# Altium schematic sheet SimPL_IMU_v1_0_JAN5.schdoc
size 302 x 236 mm
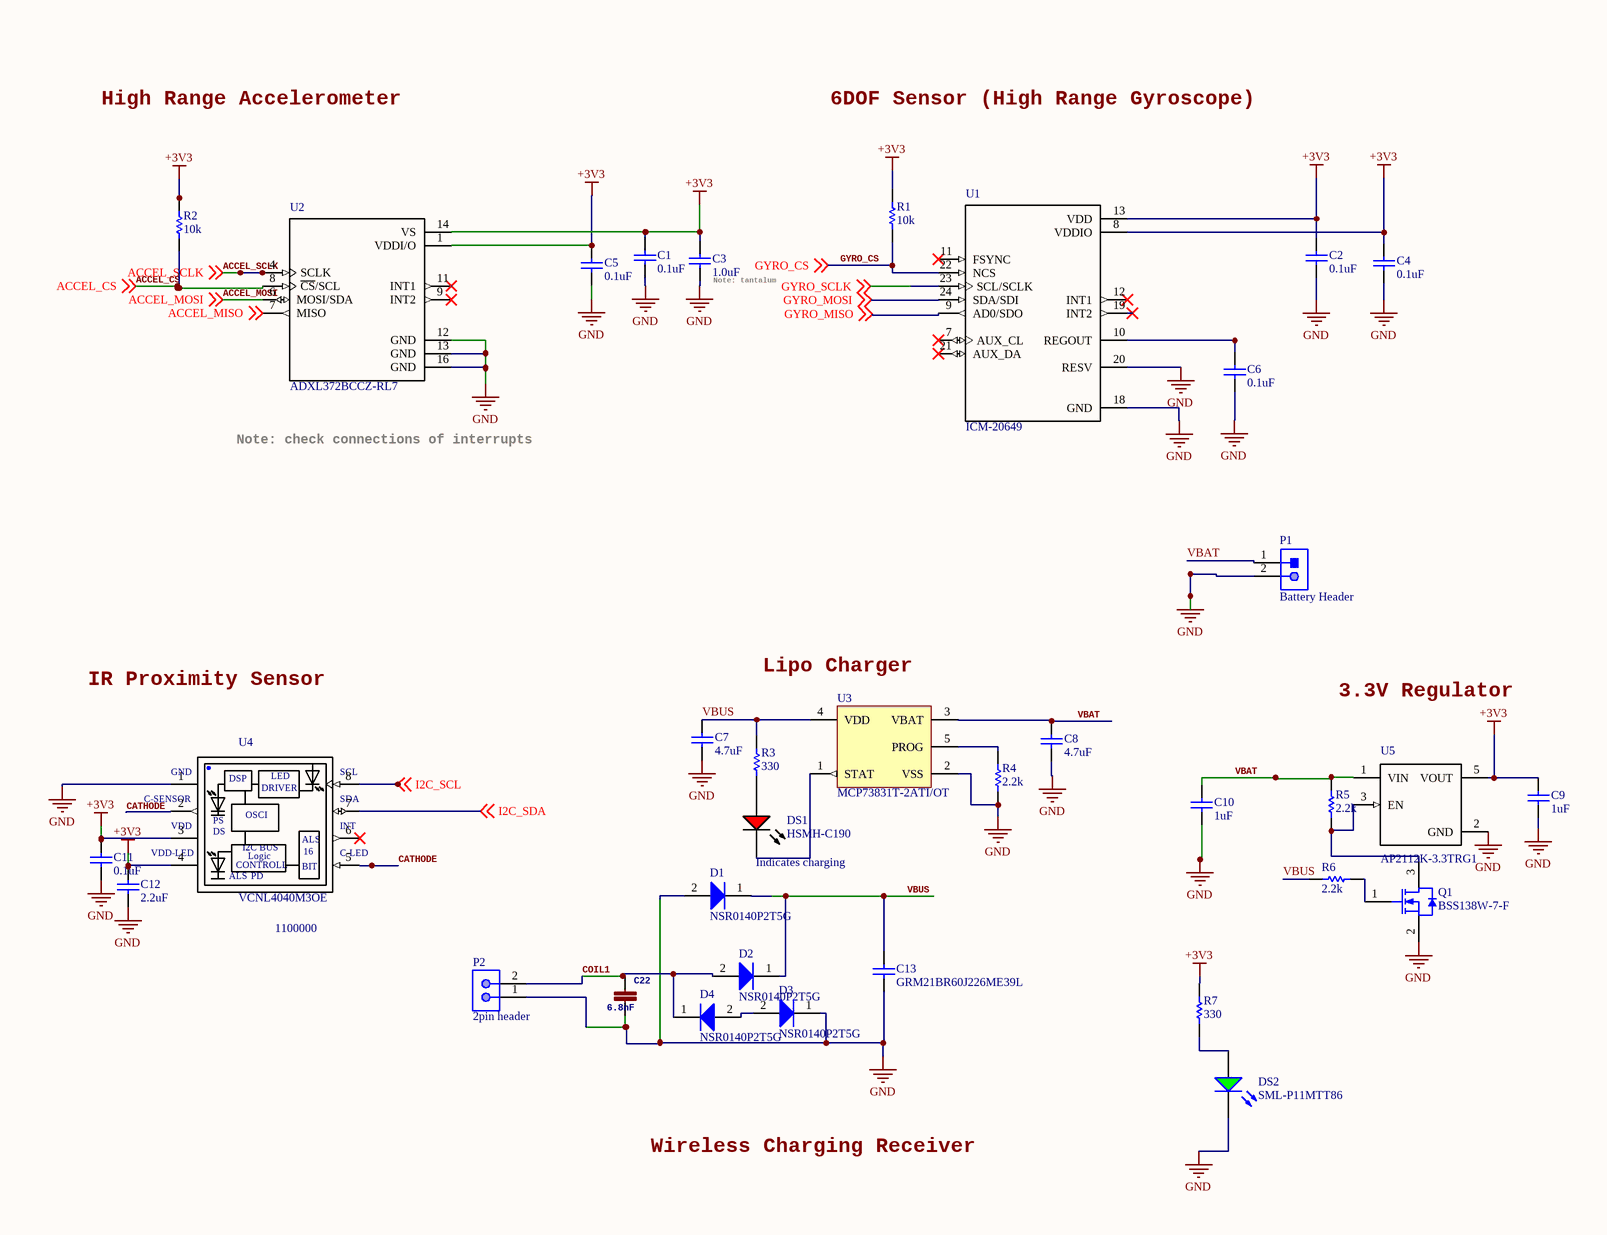
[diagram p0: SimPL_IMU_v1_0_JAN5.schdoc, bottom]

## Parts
C1  0.1uF  [CAPC0603X33X15LL03T05]
C2  0.1uF  [CAPC0603X33X15LL03T05]
C3  1.0uF  [CAPC1005X70X10LL20T00]
C4  0.1uF  [CAPC0603X33X15LL03T05]
C5  0.1uF  [CAPC0603X33X15LL03T05]
C6  0.1uF  [CAPC0603X33X15LL03T05]
C7  4.7uF  [CAPC1005X55X25NL05T10]
C8  4.7uF  [CAPC1005X55X25NL05T10]
C9  1uF  [CAPC1005X55X25NL05T10]
C10  1uF  [CAPC1005X55X25NL05T10]
C11  0.1uF  [CAPC0603X33X15LL03T05]
C12  2.2uF  [CAPC1005X70X10NL20T00]
C13  GRM21BR60J226ME39L  [CAPC2013X140X45NL15T25]
C22  6.8nF  [0402]
D1  NSR0140P2T5G  [ONSC-SOD-923-2-514AA-01_D_V]
D2  NSR0140P2T5G  [ONSC-SOD-923-2-514AA-01_D_V]
D3  NSR0140P2T5G  [ONSC-SOD-923-2-514AA-01_D_V]
D4  NSR0140P2T5G  [ONSC-SOD-923-2-514AA-01_D_V]
DS1  HSMH-C190  [AVAG-HSMX-C190_V]
DS2  SML-P11MTT86  [ROHM-SML-P11MT_V]
P1  Battery Header  [JST-S2B-PH-K-S_V]
P2  2pin header  [AMPH-68000-102HLF_V]
Q1  BSS138W-7-F  [DIOD-SOT323-3_V]
R1  10k  [RESC0603X26X15NL03T05]
R2  10k  [RESC0603X26X15NL03T05]
R3  330  [RESC1005X40X25NL05T05]
R4  2.2k  [RESC1005X40X25NL10T10]
R5  2.2k  [RESC1005X40X25NL10T10]
R6  2.2k  [RESC1005X40X25NL10T10]
R7  330  [RESC1005X40X25ML05T05]
U1  ICM-20649  [*QFN40P300X300X95-24N]
U2  ADXL372BCCZ-RL7  [*PQFN50P322X300X114-16N]
U3  MCP73831T-2ATI/OT  [SOT-23-OT5_M]
U4  VCNL4040M3OE  [*VISHAY_VCNL4040_4X2X1.1]
U5  AP2112K-3.3TRG1  [*SOT95P285X140-5N]

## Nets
+3V3: C1.2 C2.2 C3.2 C4.2 C5.2 C9.2 C11.2 C12.2 R1.2 R2.2 R7.2 U1.8(VDDIO) U1.13(VDD) U2.1(VDDI/O) U2.14(VS) U4.3(VDD) U4.4(VDD-LED) U5.5(VOUT)
GND: C1.1 C2.1 C3.1 C4.1 C5.1 C6.1 C7.1 C8.1 C9.1 C10.1 C11.1 C12.1 C13.1 C22.2 D1.2(A) D3.1(K) DS2.2(K) P1.2 P2.1 Q1.2(S) R4.1 U1.18(GND) U1.20(RESV) U2.12(GND) U2.13(GND) U2.16(GND) U3.2(VSS) U4.1(GND) U5.2(GND)
ACCEL_CS: R2.1 U2.8(~{CS}/SCL) ; off-sheet ACCEL_CS
ACCEL_MISO: U2.7(MISO) ; off-sheet ACCEL_MISO
ACCEL_MOSI: U2.6(MOSI/SDA) ; off-sheet ACCEL_MOSI
ACCEL_SCLK: U2.4(SCLK) ; off-sheet ACCEL_SCLK
CATHODE: U4.2(C-SENSOR) U4.5(C-LED)
COIL1: C22.1 D2.2(A) D4.1(K) P2.2
GYRO_CS: R1.1 U1.22(NCS) ; off-sheet GYRO_CS
GYRO_MISO: U1.9(AD0/SDO) ; off-sheet GYRO_MISO
GYRO_MOSI: U1.24(SDA/SDI) ; off-sheet GYRO_MOSI
GYRO_SCLK: U1.23(SCL/SCLK) ; off-sheet GYRO_SCLK
I2C_SCL: U4.8(SCL) ; off-sheet I2C_SCL
I2C_SDA: U4.7(SDA) ; off-sheet I2C_SDA
VBAT: C8.2 C10.2 P1.1 R5.2 U3.3(VBAT) U5.1(VIN)
VBUS: C7.2 C13.2 D1.1(K) D2.1(K) R3.2 R6.2 U3.4(VDD)
NetC6_2: C6.2 U1.10(REGOUT)
NetD3_2: D3.2(A) D4.2(A)
NetDS1_1: DS1.1(A) R3.1
NetDS1_2: DS1.2(K) U3.1(STAT)
NetDS2_1: DS2.1(A) R7.1
NetQ1_1: Q1.1(G) R6.1
NetQ1_3: Q1.3(D) R5.1 U5.3(EN)
NetR4_2: R4.2 U3.5(PROG)

Not connected (* = marked no-connect by the designer): U1 7(AUX_CL)* 11(FSYNC)* 12(INT1)* 19(INT2)* 21(AUX_DA)*; U2 9(INT2)* 11(INT1)*; U4 6(INT)*

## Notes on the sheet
- High Range Accelerometer
- 6DOF Sensor (High Range Gyroscope)
- (near C3) Note: tantalum
- Note: check connections of interrupts
- IR Proximity Sensor
- (near U3) Lipo Charger
- 3.3V Regulator
- Indicates charging
- 1100000
- Wireless Charging Receiver

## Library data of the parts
C1 C2 C4-C6 C11 = CMP-2010-01264-1: Part Number: GRM033R61A104KE15D; Manufacturer: Murata
C3 = CMP-2008-00066-1: Part Number: TACK105M010QTA; Manufacturer: AVX Interconnect / Elco
C7 C8 = CMP-2008-04549-1: Part Number: GRM155R60J475ME47D; Manufacturer: Murata
C9 C10 = CMP-2008-04556-1: Part Number: GRM155R61A105KE15D; Manufacturer: Murata
C12 = CMP-2008-00070-1: Part Number: TACK225M006QTA; Manufacturer: AVX Interconnect / Elco
C13 = CMP-2007-03385-1: Manufacturer: Murata
C22 = 0.1UF-0402-16V-10%: 0.1ÂµF ceramic capacitors    A capacitor is a passive two-terminal electrical component used to store electrical energy temporarily in an electric field.; Part Number: CC0402KRX7R9BB682; GateName_1: G$1; SymbolName_1: CAP; DeviceSetName: 0.1UF; PROD_ID: CAP-12416
D1-D4 = CMP-1055-00493-1: Schottky Barrier Diode, 2-Pin SOD-923, Pb-Free, Tape and Reel; Manufacturer: On Semiconductor; IFSM Max (A): 0.5; Configuration: Single
DS1 = CMP-1744-00004-1: LED Uni-Color Red, 65 mW, 20 mA, -40 to 85 degC, 2-Pin SMD, RoHS, Tape and Reel; Connector Type: USB; Gender: Male; Current Rating: 1 A
DS2 = CMP-2000-07126-1: LED Green, 54 mW, 20 mA, -40 to 85 degC, 2-Pin SMD, RoHS, Tape and Reel; Manufacturer: Lite-On Inc.; Part Number: LTST-C170KGKT; Lens Type: Clear; Intensity: 2.1mcd; Forward Voltage: 1.9V; Forward (Drive) Current: 20mA
P1 = CMP-1755-00004-1: Male Header, Pitch 2 mm, 1 x 2 Position, Height 4.8 mm, Tail Length 3.4 mm, -25 to 85 degC, RoHS, Bulk; Case\Package: Radial; Tolerance: 20%; Capacitance: 10 uF; Voltage Rating (DC): 50 V
P2 = CMP-2000-05666-1: Male Header, Pitch 2.54 mm, 1 x 2 Position, Height 8.38 mm, Tail Length 2.41 mm, RoHS, Bulk; Number of Positions: 2; Insulation Resistance: 5000MOhms; Voltage Rating: 1.5kV; Mounting Angle: Vertical; Pitch: 2.54mm; Brand: FCI; Current Rating: 3A; Mating Post Length: 5.84mm
Q1 = CMP-2000-05968-1: N-Channel Enhancement Mode Mosfet, 50 V, 200 mA, -55 to 150 degC, 6-Pin SOT-323, RoHS, Tape and Reel; Typical Turn-Off Delay Time: 20ns; Number of Channels: 1Channel; Type: EnhancementModeFieldEffectTransistor; Brand: DiodesIncorporated; Vds - Drain-Source Breakdown Voltage: 75V; Vgs - Gate-Source Voltage: 20V; Rds On - Drain-Source Resistance: 1.4Ohms; Transistor Type: 1N-Channel; Configuration: Single; Unit Weight: 0.000212oz; Pd - Power Dissipation: 200mW; Id - Continuous Drain Current: 200mA; Forward Transconductance - Min: 0.1S
R1 R2 = CMP-2004-02627-1: Part Number: ERJ-1GEF1002C; Manufacturer: Panasonic
R3 = CMP-2002-08523-1: Manufacturer: Vishay Dale; Part Number: CRCW0402330RFKED
R4-R6 = CMP-2002-05881-1: Part Number: ERA2AEB222X; Manufacturer: Panasonic
R7 = CMP-2002-01143-1: Manufacturer: Panasonic; Part Number: ERJ2RKF3300X
U1 = ICM-20649: Wide-Range 6-Axis MEMS MotionTracking Device for Sports and High Impact Applications; MF: TDK InvenSense
U2 = ADXL372BCCZ-RL7: / Accelerometer Triple Â±200g 2.5V 16-Pin LGA T/R /; MF: Analog Devices
U3 = CMP-0133-00144-1: Miniature Single-Cell, Fully Integrated Li-Ion, Li-Polymer Charge Management Controller, 4.2V, 5-Pin SOT-23, Industrial Temperature, Tape and Reel
U4 = VCNL4040M3OE: VCNL4040 Series 3.6 V 200 mm 16 Bit I2C SMT Proximity and Ambient Light Sensor; MF: Vishay
U5 = AP2112K-3.3TRG1: AP2112 Series 0.6 A 3.3 V Fixed Output SMT LDO Linear Regulator - SOT23-5; MF: Diodes Inc.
